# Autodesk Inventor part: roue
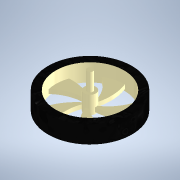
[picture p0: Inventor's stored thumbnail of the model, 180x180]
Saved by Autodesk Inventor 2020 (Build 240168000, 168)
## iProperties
Part Number: roue
Material: Nylon, disulfure de molybdène
Document SubType Name: Modeling
Designer: Buhl
Density: 1.43564 g/cm^3
Appearance: Nylon 6
Mass: 8 g
Surface Area: 44.977 cm^2
Volume: 5.57245 cm^3
Author: Buhl
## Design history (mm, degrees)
sketch "Esquisse1"
  geometry: L1 (1.5, 0)-(3, 0); L2 (3, 0)-(3, -6); L3 (3, -9)-(0, -9); L4 (0, -9)-(0, 0); L5 (0, -9)-(3, -9); L6 (17.5, -6)-(3, -6); L7 (0, -6)-(0, -9); L8 (17.5, -9)-(21.5, -9); L9 (21.5, -9)-(21.5, 0); L10 (21.5, 0)-(17.5, 0); L11 (17.5, 0)-(17.5, -6); L12 (0, -9)-(1.5, -9); L13 (1.5, 0)-(1.5, 9.069); L14 (1.5, 9.069)-(0, 9.069); L15 (0, 9.069)-(0, -9); L16 (3, -9)-(3, -8.105); L17 (3, -8.105)-(17.5, -8.105); L18 (17.5, -8.105)-(17.5, -9)
  constraints: 36 end point, 8 parallel, 4 horizontal, 3 perpendicular, 1 point on line
  dimensions: "d0" = 9 distance between parallel lines of L1 L3; "d1" = 3 distance between parallel lines of L5 L6; "d2" = 4 distance between parallel lines of L9 L11; "d3" = 3 distance between parallel lines of L4 L2; "d10" = 21.5 distance between parallel lines of L9 L4
revolve "Révolution1" sketch "Esquisse1" stored, may be unused: angle "d4" = 90 deg
sketch "Esquisse2"
  geometry: A1 r 17.5 centre (0, 0) between (9.275, 14.84) and (16.511, 5.799) reference; A2 r 3 centre (0, 0) between (0, 3) and (2.164, 2.077) reference; A3 r 19.522 centre (18.819, -2.189) between (9.275, 14.84) and (0, 3); A4 r 24.81 centre (15.283, -18.98) between (16.511, 5.799) and (2.164, 2.077); A5 r 24.258 centre (-5.498, -4.401) between (16.511, 5.799) and (9.275, 14.84); A6 r 2.989 centre (0.008, 0.007) between (2.164, 2.077) and (2.164, 2.077); 1 further point
  constraints: 14 point on circle, 4 centre point, 1 tangent
extrude "Extrusion1" cut sketch "Esquisse2" distance "d5" = 10; taper "d6" = 0 deg
pattern_circular "Réseau circulaire1" dims angle "d8" = 360 deg
node "Solide1"
